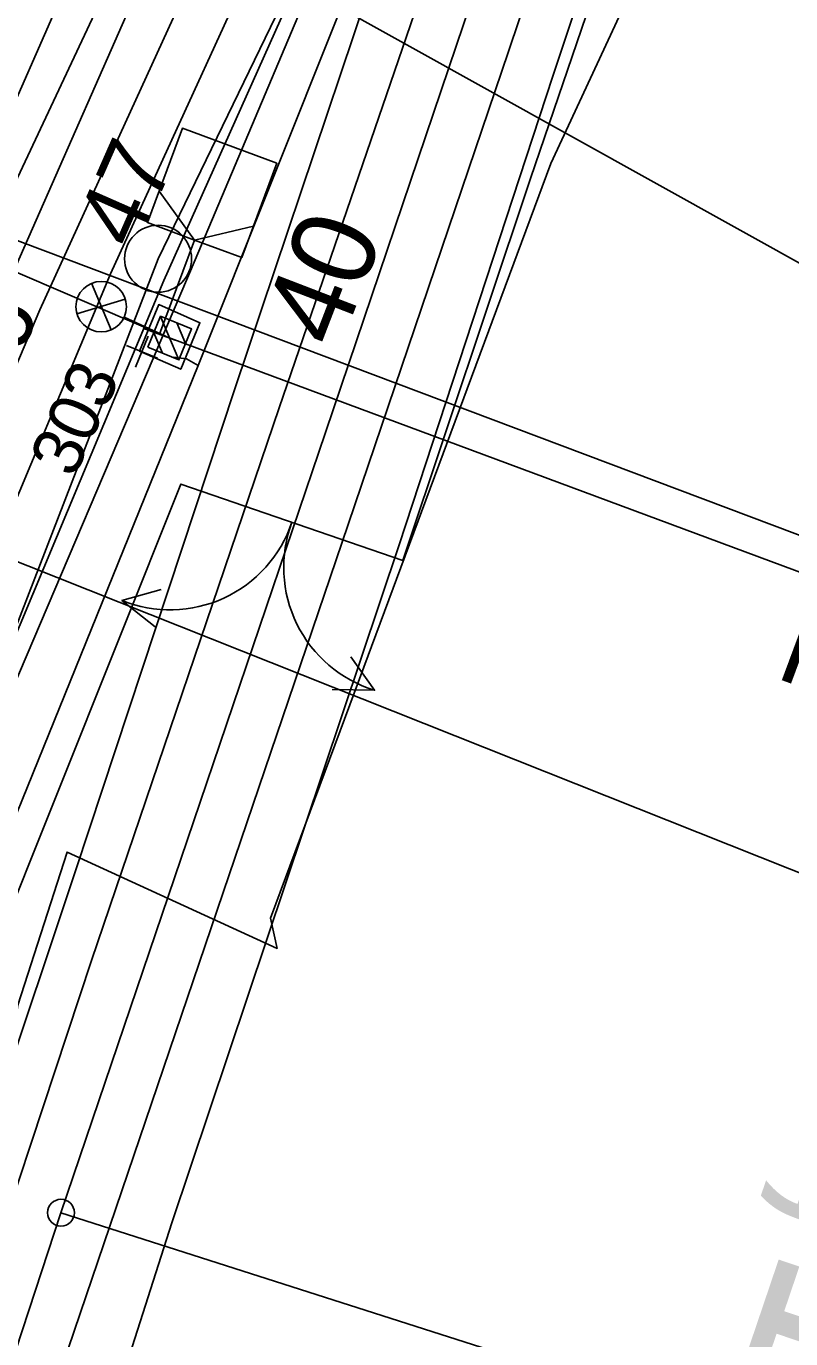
# Model space of a CAD drawing. Extents: x -598638 to -597933, y -1164002 to -1161904.
# Drawn here: x -598203.15 to -598180.34, y -1162996.25 to -1162957.08 of the extents above; entities that cross this region are included whole.
import ezdxf

# ---------------------------------------------------------------- set-up
doc = ezdxf.new("R2010")
doc.units = 0
for name, color, linetype in [('Vrstva 1', 7, 'Continuous'), ('Vrstva 11', 7, 'Continuous'), ('Vrstva 12', 7, 'Continuous'), ('Vrstva 17', 7, 'Continuous'), ('Vrstva 25', 7, 'Continuous'), ('Vrstva 26', 7, 'Continuous'), ('Vrstva 31', 7, 'Continuous'), ('Vrstva 4', 7, 'Continuous'), ('Vrstva 43', 7, 'Continuous'), ('Vrstva 44', 7, 'Continuous'), ('Vrstva 51', 7, 'Continuous'), ('Vrstva 6', 7, 'Continuous'), ('Vrstva 7', 7, 'Continuous')]:
    doc.layers.add(name, color=color, linetype=linetype)

msp = doc.modelspace()

# ---------------------------------------------------------------- linework, layer by layer
at = {"layer": 'Vrstva 1'}
for p, q in [((-598210.162, -1162970.38), (-598089.889, -1163018.237)), ((-598167.268, -1163003.634), (-598202.116, -1162992.486))]:
    msp.add_line(p, q, dxfattribs=at)
for points in [[(-598240.169, -1163146.755), (-598239.921, -1163130.309), (-598239.07, -1163113.566), (-598238.926, -1163111.785), (-598238.259, -1163103.539), (-598237.54, -1163096.536), (-598235.247, -1163078.679), (-598233.075, -1163065.413), (-598229.628, -1163048.216), (-598226.08, -1163033.339), (-598219.335, -1163009.739), (-598213.514, -1162992.625), (-598208.094, -1162978.373), (-598205.572, -1162972.188), (-598202.745, -1162965.549), (-598196.38, -1162951.607), (-598188.854, -1162936.558), (-598181.238, -1162922.581)], [(-598180.286, -1162928.035), (-598182.126, -1162933.482), (-598183.238, -1162936.76), (-598184.095, -1162939.282), (-598186.438, -1162946.204), (-598190.315, -1162957.646), (-598194.225, -1162969.204), (-598198.163, -1162980.824), (-598202.116, -1162992.486)], [(-598202.116, -1162992.486), (-598204.991, -1163001.228), (-598207.601, -1163009.698), (-598209.68, -1163016.837), (-598211.609, -1163023.823), (-598213.423, -1163030.852), (-598215.155, -1163037.97), (-598216.832, -1163045.299), (-598218.693, -1163054.151), (-598220.229, -1163062.168), (-598221.656, -1163070.154)]]:
    msp.add_lwpolyline(points, dxfattribs=at)
msp.add_circle((-598202.116, -1162992.486), 0.4, dxfattribs=at)
msp.add_circle((-598202.116, -1162992.486), 0.4, dxfattribs=at)
at = {"layer": 'Vrstva 11'}
for p, q in [((-598198.6, -1162967.041), (-598199.144, -1162965.74)), ((-598199.09, -1162966.84), (-598199.345, -1162966.231)), ((-598198.397, -1162966.555), (-598198.655, -1162965.938))]:
    msp.add_line(p, q, dxfattribs=at)
for points in [[(-598216.53, -1162958.8), (-598198.87, -1162966.39)], [(-598199.522, -1162966.663), (-598199.143, -1162965.738), (-598198.218, -1162966.117), (-598198.597, -1162967.042), (-598199.522, -1162966.663)]]:
    msp.add_lwpolyline(points, dxfattribs=at)
msp.add_lwpolyline([(-598199.522, -1162966.663), (-598199.143, -1162965.738), (-598198.218, -1162966.117), (-598198.597, -1162967.042)], close=True, dxfattribs=at)
at = {"layer": 'Vrstva 12'}
msp.add_lwpolyline([(-598199.77, -1162966.78), (-598199.2, -1162965.39), (-598197.97, -1162965.93), (-598198.54, -1162967.32), (-598199.77, -1162966.78)], dxfattribs=at)
at = {"layer": 'Vrstva 17'}
for p, q in [((-598200.298, -1162974.221), (-598199.302, -1162975)), ((-598192.759, -1162976.896), (-598194.024, -1162976.872))]:
    msp.add_line(p, q, dxfattribs=at)
for points in [[(-598160.869, -1162916.03), (-598165.61, -1162912.687), (-598173.226, -1162925.769), (-598179.204, -1162936.08), (-598180.398, -1162938.876), (-598184.227, -1162950.256), (-598188.104, -1162961.627), (-598191.911, -1162973.022), (-598198.535, -1162970.746), (-598204.125, -1162984.71), (-598208.617, -1162995.882), (-598214.208, -1163009.83), (-598215.031, -1163012.689), (-598218.215, -1163027.367), (-598221.453, -1163042.038), (-598223.962, -1163053.782), (-598226.517, -1163065.417), (-598227.975, -1163080.383)], [(-598199.302, -1162975), (-598200.298, -1162974.221), (-598199.123, -1162973.895)], [(-598194.024, -1162976.872), (-598192.759, -1162976.896), (-598193.467, -1162975.902)]]:
    msp.add_lwpolyline(points, dxfattribs=at)
for centre, start, end in [((-598198.861, -1162970.666), 247.9809, 341.5008), ((-598191.635, -1162973.23), 159.4313, 252.9512)]:
    msp.add_arc(centre, 3.834, start, end, dxfattribs=at)
at = {"layer": 'Vrstva 25'}
for p, q in [((-598201.202, -1162964.751), (-598200.621, -1162966.142)), ((-598201.639, -1162965.667), (-598200.198, -1162965.225)), ((-598200.234, -1162965.765), (-598198.87, -1162966.39))]:
    msp.add_line(p, q, dxfattribs=at)
msp.add_circle((-598200.915, -1162965.452), 0.754, dxfattribs=at)
at = {"layer": 'Vrstva 26'}
for points in [[(-598211.382, -1162940.065), (-598193.601, -1162950.161), (-598191.584, -1162951.092), (-598198.026, -1162967.205), (-598208.688, -1162993.504), (-598209.03, -1162994.474), (-598214.707, -1163009.33), (-598218.558, -1163024.082), (-598220.34, -1163031.684), (-598220.756, -1163034.417), (-598224.218, -1163049.876), (-598227.646, -1163065.71), (-598228.067, -1163068.213), (-598230.531, -1163097), (-598231.676, -1163107.807), (-598231.723, -1163120.907), (-598232.574, -1163129.537), (-598231.426, -1163150.759)], [(-598198.026, -1162967.205), (-598198.366, -1162967.012), (-598198.765, -1162966.96)]]:
    msp.add_lwpolyline(points, dxfattribs=at)
at = {"layer": 'Vrstva 31'}
for points in [[(-598153.447, -1162881.401), (-598158.917, -1162890.286), (-598163.962, -1162898.735), (-598165.887, -1162906.436), (-598166.192, -1162908.567), (-598166.64, -1162910.14), (-598167.818, -1162914.276), (-598168.011, -1162918.252), (-598168.382, -1162919.355), (-598171.993, -1162924.817), (-598180.701, -1162940.523), (-598180.438, -1162944.574), (-598182.04, -1162949.425), (-598187.501, -1162961.184)], [(-598187.501, -1162961.184), (-598193.206, -1162976.554), (-598195.86, -1162983.693), (-598195.667, -1162984.598), (-598201.933, -1162981.727), (-598203.4, -1162986.295), (-598203.688, -1162988.375), (-598209.584, -1163004.545), (-598216.013, -1163026.631), (-598221.666, -1163051.523), (-598225.684, -1163073.174), (-598227.353, -1163095.356), (-598224.072, -1163125.91), (-598223.968, -1163127.205), (-598223.831, -1163129.669), (-598219.355, -1163146.93), (-598215.178, -1163168.467), (-598212.475, -1163189.221), (-598207.807, -1163230.178)]]:
    msp.add_lwpolyline(points, dxfattribs=at)
at = {"layer": 'Vrstva 4'}
for points in [[(-598236.122, -1163097.625), (-598233.737, -1163078.205), (-598231.603, -1163064.919), (-598228.204, -1163048.211), (-598224.742, -1163033.919), (-598217.308, -1163008.105), (-598211.392, -1162991.093), (-598206.621, -1162978.751), (-598200.642, -1162964.474), (-598195.034, -1162952.232), (-598186.946, -1162936.115), (-598183.34, -1162929.36)], [(-598234.285, -1163099.455), (-598231.787, -1163078.342), (-598229.816, -1163067.198), (-598225.948, -1163048.912), (-598222.74, -1163035.209), (-598216.053, -1163011.484), (-598208.869, -1162991.272), (-598204.619, -1162979.312), (-598198.109, -1162964.057), (-598193.443, -1162953.005), (-598185.456, -1162937.387), (-598183.707, -1162933.568)]]:
    msp.add_lwpolyline(points, dxfattribs=at)
at = {"layer": 'Vrstva 43'}
msp.add_circle((-598199.219, -1162964.022), 1, dxfattribs=at)
at = {"layer": 'Vrstva 44'}
for points in [[(-598295.758, -1163493.483), (-598278.118, -1163452.874), (-598264.209, -1163410.565), (-598254.468, -1163367.19), (-598248.62, -1163321.577), (-598253.497, -1163320.887), (-598249.615, -1163272.581), (-598247.635, -1163222.481), (-598247.486, -1163176.779), (-598247.442, -1163130.148), (-598244.014, -1163084.171), (-598235.33, -1163037.762), (-598224.817, -1163002.559), (-598219.379, -1163002.169), (-598206.652, -1162968.487), (-598191.401, -1162936.053), (-598173.754, -1162904.506), (-598155.689, -1162873.083), (-598136.14, -1162838.446), (-598116.776, -1162804.197)], [(-598214.433, -1163003.397), (-598199.219, -1162964.022), (-598185.65, -1162936.04), (-598163.291, -1162895.981), (-598150.219, -1162876.092), (-598140.441, -1162856.726), (-598110.998, -1162804.439)]]:
    msp.add_lwpolyline(points, dxfattribs=at)
at = {"layer": 'Vrstva 51'}
for points in [[(-598243.76, -1163139.382), (-598243.393, -1163128.836), (-598242.662, -1163113.52), (-598241.121, -1163096.732), (-598238.542, -1163077.297), (-598236.364, -1163063.881), (-598233.006, -1163047.35), (-598229.452, -1163032.186), (-598222.566, -1163008.635), (-598216.788, -1162991.447), (-598211.314, -1162977.141), (-598198.954, -1162949.031), (-598191.954, -1162935.136), (-598181.215, -1162915.654), (-598172.367, -1162900.092), (-598146.639, -1162854.694), (-598125.435, -1162817.431), (-598123.403, -1162813.873), (-598093.874, -1162762.323), (-598071.494, -1162722.83), (-598058.726, -1162701.732), (-598043.403, -1162678.606), (-598026.165, -1162652.845)], [(-598239.095, -1163097.092), (-598236.576, -1163077.501), (-598234.309, -1163064.254), (-598231.064, -1163047.867), (-598227.331, -1163032.522), (-598220.677, -1163009.309), (-598214.847, -1162992.197), (-598209.449, -1162977.846), (-598197.189, -1162949.981), (-598190.09, -1162935.876), (-598179.544, -1162916.618), (-598170.666, -1162900.915), (-598144.793, -1162855.5), (-598123.538, -1162818.503), (-598121.573, -1162814.996), (-598092.208, -1162763.361), (-598069.503, -1162724.253), (-598055.71, -1162703.114), (-598040.468, -1162680.627), (-598023.352, -1162655.056), (-598026.165, -1162652.845)], [(-598221.478, -1163080.78), (-598219.566, -1163067.136), (-598219.219, -1163065.098), (-598216.814, -1163053.054), (-598216.308, -1163050.154), (-598213.455, -1163037.18), (-598209.254, -1163020.993), (-598206.671, -1163012.257), (-598205.894, -1163009.286), (-598205.807, -1163008.944), (-598201.906, -1162996.551), (-598193.548, -1162971.953), (-598188.761, -1162957.834), (-598185.003, -1162946.673), (-598180.831, -1162934.422), (-598177.192, -1162923.967), (-598173.595, -1162914.671), (-598168.64, -1162904.115), (-598164.118, -1162895.651), (-598162.659, -1162896.444)], [(-598162.659, -1162896.444), (-598167.315, -1162905.247), (-598172.294, -1162915.543), (-598175.907, -1162924.588), (-598179.431, -1162935.039), (-598183.642, -1162947.197), (-598187.437, -1162958.573), (-598192.02, -1162972.557), (-598198.809, -1162992.788), (-598204.748, -1163011.314), (-598205.213, -1163012.907), (-598207.438, -1163020.452), (-598209.822, -1163028.442), (-598211.787, -1163036.541), (-598212.573, -1163039.781), (-598214.64, -1163049.347), (-598215.473, -1163053.325), (-598217.705, -1163064.512), (-598218.096, -1163067.37), (-598220.007, -1163080.081)], [(-598234.985, -1163097.818), (-598232.528, -1163078.41), (-598230.539, -1163066.595), (-598226.731, -1163048.661), (-598223.587, -1163035.053), (-598216.724, -1163011.435), (-598209.696, -1162991.235), (-598205.138, -1162979.218), (-598199.051, -1162964.673), (-598193.758, -1162952.835), (-598185.502, -1162936.812), (-598183.707, -1162933.568), (-598182.431, -1162929.818), (-598183.34, -1162929.36)], [(-598225.987, -1163079.977), (-598225.433, -1163075.24), (-598224.4, -1163068.446), (-598223.276, -1163062.974), (-598221.56, -1163053.654), (-598219.088, -1163041.864), (-598218.289, -1163038.506), (-598215.72, -1163028.247), (-598212.289, -1163016.175), (-598208.971, -1163004.649), (-598206.367, -1162996.288), (-598201.674, -1162982.251), (-598196.929, -1162967.908), (-598191.009, -1162950.285), (-598184.021, -1162931.293), (-598183.109, -1162931.599)], [(-598183.109, -1162931.599), (-598185.779, -1162939.427), (-598189.427, -1162950.443), (-598195.6, -1162968.473), (-598201.203, -1162984.962), (-598205.181, -1162996.978), (-598207.823, -1163005.387), (-598207.873, -1163005.495), (-598211.27, -1163016.966), (-598211.421, -1163017.483), (-598214.449, -1163028.785), (-598217.013, -1163039.126), (-598217.753, -1163042.541), (-598220.273, -1163054.386), (-598221.987, -1163063.395), (-598223.013, -1163069.069), (-598224.075, -1163075.616), (-598224.553, -1163080.356)]]:
    msp.add_lwpolyline(points, dxfattribs=at)
at = {"layer": 'Vrstva 6'}
msp.add_line((-598195.337, -1162955.666), (-598160.384, -1162975.116), dxfattribs=at)
at = {"layer": 'Vrstva 7'}
for p, q in [((-598209.019, -1162961.375), (-598162.142, -1162979.022)), ((-598198.129, -1162963.464), (-598199.174, -1162966.276)), ((-598199.643, -1162966.102), (-598198.705, -1162966.45)), ((-598199.236, -1162966.985), (-598200.162, -1162966.607)), ((-598199.51, -1162966.333), (-598199.888, -1162967.259)), ((-598199.174, -1162966.276), (-598161.679, -1162980.209))]:
    msp.add_line(p, q, dxfattribs=at)
for points in [[(-598198.129, -1162963.464), (-598196.723, -1162963.986), (-598195.678, -1162961.174), (-598198.49, -1162960.129), (-598199.535, -1162962.941), (-598198.129, -1162963.464)], [(-598199.186, -1162962.002), (-598198.129, -1162963.464), (-598196.374, -1162963.047)]]:
    msp.add_lwpolyline(points, dxfattribs=at)

# ---------------------------------------------------------------- texts
at = {"layer": 'Vrstva 11'}
msp.add_text('40', height=2.5, rotation=68.945, dxfattribs=at).set_placement((-598193.818, -1162966.766))
at = {"layer": 'Vrstva 25'}
msp.add_text('303', height=1.5, rotation=65.3825, dxfattribs=at).set_placement((-598201.733, -1162970.603))
at = {"layer": 'Vrstva 43'}
for s, rotation, p in [('47', 66.2515, (-598199.895, -1162963.806)), ('66', 66.9349, (-598203.915, -1162968.343))]:
    msp.add_text(s, height=2, rotation=rotation, dxfattribs=at).set_placement(p)
at = {"layer": 'Vrstva 7'}
for s, height, rotation, p in [('km 11,923', 2.5, 339.6146, (-598180.816, -1162976.518)), ('0,1', 6, 251.2752, (-598178.354, -1162986.968))]:
    msp.add_text(s, height=height, rotation=rotation, dxfattribs=at).set_placement(p)

doc.saveas('drawing.dxf')
